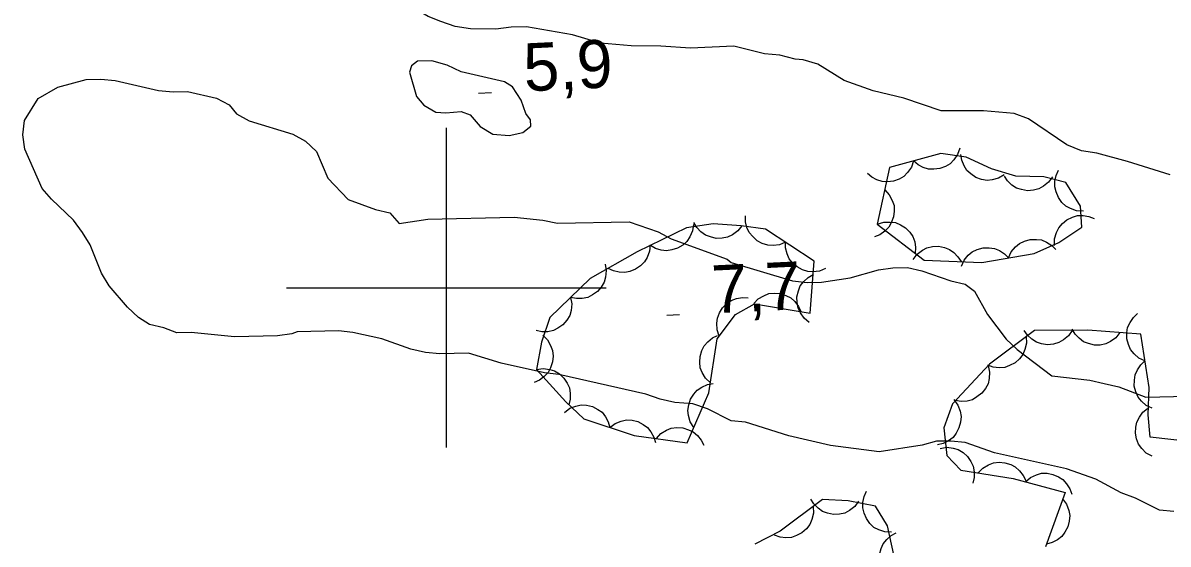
# Model space of a CAD drawing. Extents: x 336540 to 340074, y 5572036 to 5573747.
# Drawn here: x 336773.5 to 336845.2, y 5572783.9 to 5572816.6 of the extents above; entities that cross this region are included whole.
import ezdxf

# ---------------------------------------------------------------- set-up
doc = ezdxf.new("R2010")
doc.units = 0
for name, color, linetype in [('Niveau 2', 7, 'Continuous'), ('Niveau 3', 7, 'Continuous'), ('Niveau 44', 7, 'Continuous'), ('Niveau 61', 7, 'Continuous')]:
    doc.layers.add(name, color=color, linetype=linetype)

msp = doc.modelspace()

# ---------------------------------------------------------------- linework, layer by layer
at = {"layer": 'Niveau 2'}
for points in [[(336805.01, 5572816.34), (336804.05, 5572816.32), (336803.1, 5572816.18), (336801.52, 5572816.2), (336800.56, 5572816.35), (336799.65, 5572816.67), (336798.86, 5572816.99), (336798.11, 5572817.42)], [(336845.31, 5572807.07), (336842.65, 5572807.91), (336840.72, 5572808.43), (336839.76, 5572808.57), (336838.85, 5572808.95), (336836.45, 5572810.58), (336835.54, 5572810.9), (336833.62, 5572811.08), (336830.98, 5572811.08), (336828.65, 5572811.87), (336826.72, 5572812.33), (336824.91, 5572812.97), (336823.25, 5572814), (336822.34, 5572814.26), (336821.84, 5572814.3), (336820.87, 5572814.56), (336819.91, 5572814.65), (336817.99, 5572815.12), (336815.29, 5572815), (336813.43, 5572815.13), (336811.57, 5572815.14), (336809.65, 5572815.32), (336807.89, 5572815.84), (336805.01, 5572816.34)], [(336802.92, 5572809.61), (336803.94, 5572809.52), (336804.78, 5572809.71), (336805.28, 5572810.12), (336805.27, 5572810.51), (336804.98, 5572810.9), (336804.68, 5572811.74), (336804.15, 5572812.57), (336803.64, 5572812.9), (336800.92, 5572813.51), (336800.06, 5572813.94), (336799.1, 5572814.2), (336798.2, 5572814.18), (336797.81, 5572813.89), (336797.7, 5572813.5), (336798.13, 5572811.98), (336798.6, 5572811.43), (336799.34, 5572811), (336799.96, 5572810.95), (336800.92, 5572811.03), (336801.49, 5572810.82), (336802.12, 5572810.1), (336802.92, 5572809.61)], [(336803.43, 5572795.27), (336801.39, 5572795.9), (336799.59, 5572795.86), (336798.69, 5572795.95), (336797.78, 5572796.16), (336795.97, 5572796.79), (336794.15, 5572797.2), (336793.25, 5572797.29), (336790.66, 5572797.23), (336790.33, 5572797.11), (336789.43, 5572796.98), (336786.73, 5572796.92), (336784.02, 5572797.2), (336783.12, 5572797.17), (336782.32, 5572797.49), (336781.42, 5572797.7), (336780.73, 5572798.13), (336780.04, 5572798.79), (336778.88, 5572800.12), (336778.42, 5572800.9), (336777.7, 5572802.68), (336777.23, 5572803.46), (336776.65, 5572804.23), (336775.27, 5572805.55), (336774.69, 5572806.22), (336773.62, 5572808.67), (336773.49, 5572809.57), (336773.58, 5572810.47), (336774.45, 5572811.84), (336775.67, 5572812.55), (336777.46, 5572813.04), (336778.36, 5572813.06), (336779.27, 5572812.97), (336781.98, 5572812.35), (336782.89, 5572812.26), (336783.79, 5572812.28), (336785.6, 5572811.87), (336786.4, 5572811.44), (336786.86, 5572810.89), (336787.66, 5572810.45), (336790.38, 5572809.62), (336791.18, 5572809.18), (336791.87, 5572808.52), (336792.58, 5572806.85), (336793.85, 5572805.53), (336795.56, 5572804.89), (336796.46, 5572804.69), (336797.04, 5572804.02)], [(336797.04, 5572804.02), (336798.84, 5572804.29), (336804.24, 5572804.41), (336806.04, 5572804.23), (336806.95, 5572804.03), (336811.45, 5572804.13), (336813.27, 5572803.49), (336814.07, 5572803.06), (336817.59, 5572801.79), (336817.82, 5572801.57), (336821.67, 5572800.42), (336822.58, 5572800.33), (336823.48, 5572800.35), (336825.27, 5572800.61), (336827.06, 5572801.11), (336827.96, 5572801.24), (336828.86, 5572801.26), (336829.77, 5572801.05), (336831.58, 5572800.42), (336832.49, 5572800.22), (336833.06, 5572799.78), (336833.88, 5572798.33), (336835.05, 5572796.78), (336835.74, 5572796.12), (336837.91, 5572794.48), (336840.28, 5572794.2), (336841.19, 5572794), (336842.1, 5572793.79), (336843.8, 5572793.15), (336846.39, 5572793.21)], [(336845.54, 5572785.99), (336844.64, 5572786.08), (336843.15, 5572786.83), (336842.25, 5572787.15), (336840.65, 5572788.01), (336838.83, 5572788.65), (336834.31, 5572789.67), (336832.49, 5572790.31), (336831.59, 5572790.4), (336830.69, 5572790.38), (336829.79, 5572790.13), (336827.1, 5572789.73), (336824.05, 5572790.11), (336821.44, 5572790.73), (336818.72, 5572791.57), (336817.82, 5572791.66), (336816.34, 5572792.41), (336815.43, 5572792.73), (336814.3, 5572792.82), (336813.39, 5572793.02), (336812.49, 5572793.34), (336807.05, 5572794.57), (336806.15, 5572794.66), (336803.43, 5572795.27)]]:
    msp.add_lwpolyline(points, dxfattribs=at)
at = {"layer": 'Niveau 3'}
for p, q in [((336802.02, 5572812.19), (336802.82, 5572812.23)), ((336813.8, 5572798.29), (336814.6, 5572798.33))]:
    msp.add_line(p, q, dxfattribs=at)
at = {"layer": 'Niveau 44'}
for points in [[(336832.15, 5572808.73), (336832.01, 5572808.33), (336831.77, 5572808), (336831.55, 5572807.76), (336831.24, 5572807.58), (336830.9, 5572807.46), (336830.52, 5572807.42), (336830.19, 5572807.42), (336829.85, 5572807.53), (336829.53, 5572807.7), (336829.25, 5572807.94)], [(336829.25, 5572807.94), (336829.12, 5572807.54), (336828.88, 5572807.21), (336828.65, 5572806.97), (336828.35, 5572806.8), (336828, 5572806.67), (336827.62, 5572806.63), (336827.29, 5572806.64), (336826.96, 5572806.75), (336826.63, 5572806.92), (336826.36, 5572807.15)], [(336826.98, 5572803.97), (336829.91, 5572801.73), (336833.52, 5572801.57), (336836.8, 5572802.15), (336838.35, 5572802.82), (336839.79, 5572803.8), (336839.69, 5572805.1), (336838.79, 5572806.59), (336837.4, 5572806.95), (336835.65, 5572806.98), (336834.12, 5572807.44), (336832.54, 5572808.18), (336830.95, 5572808.4), (336827.75, 5572807.53), (336826.98, 5572803.97)], [(336834.93, 5572807.06), (336834.57, 5572806.85), (336834.17, 5572806.75), (336833.85, 5572806.71), (336833.5, 5572806.78), (336833.15, 5572806.9), (336832.84, 5572807.12), (336832.59, 5572807.33), (336832.41, 5572807.64), (336832.27, 5572807.98), (336832.21, 5572808.33)], [(336839.88, 5572804.79), (336839.46, 5572804.81), (336839.08, 5572804.95), (336838.79, 5572805.1), (336838.53, 5572805.34), (336838.32, 5572805.64), (336838.18, 5572806), (336838.09, 5572806.31), (336838.1, 5572806.66), (336838.18, 5572807.03), (336838.33, 5572807.35)], [(336837.94, 5572806.94), (336837.7, 5572806.6), (336837.38, 5572806.35), (336837.1, 5572806.18), (336836.76, 5572806.1), (336836.39, 5572806.07), (336836.01, 5572806.14), (336835.7, 5572806.24), (336835.41, 5572806.43), (336835.14, 5572806.69), (336834.94, 5572806.99)], [(336827.45, 5572806.12), (336827.73, 5572805.82), (336827.92, 5572805.46), (336828.03, 5572805.14), (336828.04, 5572804.79), (336828, 5572804.43), (336827.85, 5572804.07), (336827.7, 5572803.78), (336827.45, 5572803.53), (336827.14, 5572803.32), (336826.81, 5572803.19)], [(336821.24, 5572802.85), (336820.85, 5572802.69), (336820.45, 5572802.64), (336820.12, 5572802.66), (336819.78, 5572802.77), (336819.46, 5572802.94), (336819.18, 5572803.2), (336818.96, 5572803.45), (336818.82, 5572803.77), (336818.73, 5572804.13), (336818.73, 5572804.49)], [(336838.08, 5572802.64), (336838.08, 5572803.06), (336838.2, 5572803.45), (336838.34, 5572803.75), (336838.57, 5572804.01), (336838.85, 5572804.25), (336839.2, 5572804.41), (336839.51, 5572804.51), (336839.86, 5572804.52), (336840.23, 5572804.46), (336840.56, 5572804.33)], [(336805.65, 5572794.88), (336807.49, 5572792.86), (336808.61, 5572791.79), (336811.75, 5572790.75), (336815.07, 5572790.28), (336816.44, 5572793.41), (336816.95, 5572796.79), (336818.1, 5572798.32), (336819.3, 5572798.99), (336822.77, 5572798.41), (336823.03, 5572801.67), (336819.98, 5572803.67), (336818.45, 5572803.88), (336816.7, 5572804), (336815.04, 5572803.75), (336811.95, 5572802.24), (336809, 5572800.57), (336806.48, 5572798.13), (336805.96, 5572796.59), (336805.65, 5572794.88)], [(336815.47, 5572803.96), (336815.41, 5572803.55), (336815.24, 5572803.18), (336815.06, 5572802.9), (336814.8, 5572802.67), (336814.48, 5572802.48), (336814.11, 5572802.37), (336813.79, 5572802.31), (336813.44, 5572802.36), (336813.09, 5572802.46), (336812.77, 5572802.64)], [(336818.5, 5572803.88), (336818.24, 5572803.55), (336817.91, 5572803.31), (336817.61, 5572803.16), (336817.27, 5572803.1), (336816.9, 5572803.09), (336816.53, 5572803.18), (336816.22, 5572803.29), (336815.94, 5572803.5), (336815.68, 5572803.77), (336815.5, 5572804.08)], [(336826.98, 5572803.97), (336827.38, 5572804.1), (336827.78, 5572804.11), (336828.11, 5572804.08), (336828.44, 5572803.94), (336828.75, 5572803.75), (336829.01, 5572803.47), (336829.21, 5572803.21), (336829.32, 5572802.87), (336829.38, 5572802.51), (336829.36, 5572802.15)], [(336835.19, 5572801.87), (336835.36, 5572802.25), (336835.63, 5572802.55), (336835.88, 5572802.77), (336836.2, 5572802.92), (336836.55, 5572803.02), (336836.94, 5572803.02), (336837.26, 5572802.99), (336837.58, 5572802.85), (336837.9, 5572802.65), (336838.15, 5572802.39)], [(336812.75, 5572802.69), (336812.72, 5572802.28), (336812.57, 5572801.9), (336812.41, 5572801.61), (336812.15, 5572801.36), (336811.85, 5572801.15), (336811.49, 5572801.02), (336811.17, 5572800.95), (336810.82, 5572800.97), (336810.46, 5572801.05), (336810.14, 5572801.21)], [(336823.74, 5572801.2), (336823.36, 5572801.04), (336822.95, 5572801), (336822.62, 5572801.01), (336822.29, 5572801.12), (336821.97, 5572801.3), (336821.68, 5572801.56), (336821.47, 5572801.8), (336821.33, 5572802.13), (336821.24, 5572802.49), (336821.24, 5572802.85)], [(336829.22, 5572801.76), (336829.47, 5572802.1), (336829.8, 5572802.34), (336830.09, 5572802.5), (336830.43, 5572802.57), (336830.8, 5572802.59), (336831.18, 5572802.51), (336831.49, 5572802.4), (336831.77, 5572802.2), (336832.03, 5572801.93), (336832.22, 5572801.63)], [(336832.24, 5572801.34), (336832.41, 5572801.72), (336832.67, 5572802.03), (336832.92, 5572802.25), (336833.24, 5572802.4), (336833.6, 5572802.49), (336833.98, 5572802.5), (336834.31, 5572802.46), (336834.63, 5572802.32), (336834.94, 5572802.12), (336835.19, 5572801.87)], [(336809.94, 5572801.48), (336810.01, 5572801.07), (336809.96, 5572800.66), (336809.88, 5572800.34), (336809.7, 5572800.04), (336809.46, 5572799.76), (336809.14, 5572799.55), (336808.85, 5572799.39), (336808.51, 5572799.33), (336808.14, 5572799.32), (336807.78, 5572799.39)], [(336822.72, 5572797.83), (336822.4, 5572798.09), (336822.17, 5572798.42), (336822.02, 5572798.72), (336821.96, 5572799.07), (336821.95, 5572799.43), (336822.05, 5572799.81), (336822.16, 5572800.11), (336822.38, 5572800.39), (336822.65, 5572800.64), (336822.96, 5572800.82)], [(336807.78, 5572799.39), (336807.86, 5572798.98), (336807.81, 5572798.58), (336807.72, 5572798.26), (336807.54, 5572797.96), (336807.3, 5572797.68), (336806.98, 5572797.46), (336806.7, 5572797.31), (336806.35, 5572797.24), (336805.98, 5572797.23), (336805.63, 5572797.31)], [(336817.08, 5572796.97), (336816.95, 5572797.36), (336816.93, 5572797.77), (336816.97, 5572798.1), (336817.1, 5572798.42), (336817.29, 5572798.74), (336817.57, 5572799), (336817.83, 5572799.2), (336818.16, 5572799.32), (336818.53, 5572799.38), (336818.89, 5572799.37)], [(336819.24, 5572799), (336819.52, 5572799.3), (336819.88, 5572799.5), (336820.18, 5572799.63), (336820.53, 5572799.66), (336820.9, 5572799.63), (336821.26, 5572799.51), (336821.56, 5572799.37), (336821.82, 5572799.13), (336822.04, 5572798.83), (336822.19, 5572798.51)], [(336843.73, 5572795.41), (336843.35, 5572795.59), (336843.05, 5572795.86), (336842.84, 5572796.12), (336842.7, 5572796.44), (336842.61, 5572796.8), (336842.61, 5572797.18), (336842.65, 5572797.5), (336842.8, 5572797.82), (336843.01, 5572798.13), (336843.27, 5572798.38)], [(336847.56, 5572790.24), (336844.07, 5572790.65), (336843.93, 5572792.03), (336843.99, 5572793.76), (336843.47, 5572797.09), (336840.16, 5572797.34), (336836.82, 5572797.32), (336834, 5572795.22), (336831.68, 5572792.72), (336831.14, 5572791.23), (336831.33, 5572789.5), (336832.2, 5572788.57), (336835.49, 5572788.05), (336838.73, 5572787.18), (336837.51, 5572783.77)], [(336839.18, 5572797.33), (336838.95, 5572796.99), (336838.63, 5572796.73), (336838.35, 5572796.56), (336838.01, 5572796.46), (336837.64, 5572796.43), (336837.26, 5572796.49), (336836.95, 5572796.58), (336836.65, 5572796.77), (336836.38, 5572797.02), (336836.18, 5572797.32)], [(336842.17, 5572797.19), (336841.91, 5572796.86), (336841.58, 5572796.63), (336841.28, 5572796.48), (336840.94, 5572796.41), (336840.57, 5572796.41), (336840.2, 5572796.5), (336839.89, 5572796.61), (336839.61, 5572796.83), (336839.36, 5572797.1), (336839.18, 5572797.41)], [(336806.04, 5572797.02), (336806.34, 5572796.73), (336806.53, 5572796.38), (336806.65, 5572796.07), (336806.68, 5572795.72), (336806.65, 5572795.35), (336806.52, 5572794.99), (336806.37, 5572794.69), (336806.13, 5572794.44), (336805.83, 5572794.22), (336805.5, 5572794.07)], [(336816.54, 5572794.04), (336816.23, 5572794.33), (336816.02, 5572794.68), (336815.89, 5572794.98), (336815.86, 5572795.33), (336815.88, 5572795.7), (336816, 5572796.06), (336816.13, 5572796.36), (336816.37, 5572796.62), (336816.66, 5572796.86), (336816.98, 5572797.01)], [(336836.3, 5572796.94), (336836.32, 5572796.52), (336836.22, 5572796.12), (336836.1, 5572795.82), (336835.88, 5572795.54), (336835.6, 5572795.3), (336835.26, 5572795.12), (336834.96, 5572795.01), (336834.61, 5572794.99), (336834.24, 5572795.03), (336833.9, 5572795.14)], [(336833.91, 5572795.13), (336834.01, 5572794.72), (336833.98, 5572794.31), (336833.92, 5572793.99), (336833.75, 5572793.68), (336833.52, 5572793.39), (336833.22, 5572793.16), (336832.94, 5572792.98), (336832.6, 5572792.9), (336832.23, 5572792.87), (336831.87, 5572792.93)], [(336844.19, 5572792.45), (336843.82, 5572792.63), (336843.52, 5572792.9), (336843.3, 5572793.15), (336843.16, 5572793.47), (336843.07, 5572793.83), (336843.08, 5572794.22), (336843.12, 5572794.54), (336843.26, 5572794.86), (336843.47, 5572795.17), (336843.73, 5572795.41)], [(336805.65, 5572794.88), (336806.06, 5572794.94), (336806.47, 5572794.88), (336806.78, 5572794.79), (336807.08, 5572794.6), (336807.35, 5572794.34), (336807.56, 5572794.02), (336807.7, 5572793.73), (336807.76, 5572793.38), (336807.75, 5572793.01), (336807.67, 5572792.66)], [(336815.49, 5572791.25), (336815.27, 5572791.6), (336815.16, 5572791.99), (336815.12, 5572792.32), (336815.17, 5572792.67), (336815.29, 5572793.02), (336815.5, 5572793.34), (336815.71, 5572793.59), (336816, 5572793.78), (336816.34, 5572793.93), (336816.7, 5572794)], [(336831.78, 5572792.99), (336832.02, 5572792.65), (336832.16, 5572792.26), (336832.22, 5572791.94), (336832.19, 5572791.59), (336832.09, 5572791.23), (336831.91, 5572790.9), (336831.72, 5572790.63), (336831.43, 5572790.42), (336831.1, 5572790.25), (336830.75, 5572790.17)], [(336807.39, 5572792.19), (336807.72, 5572792.45), (336808.11, 5572792.59), (336808.43, 5572792.67), (336808.78, 5572792.64), (336809.14, 5572792.56), (336809.48, 5572792.38), (336809.75, 5572792.2), (336809.96, 5572791.92), (336810.14, 5572791.6), (336810.24, 5572791.25)], [(336844.19, 5572789.45), (336843.82, 5572789.64), (336843.54, 5572789.93), (336843.34, 5572790.2), (336843.21, 5572790.53), (336843.15, 5572790.89), (336843.17, 5572791.27), (336843.23, 5572791.59), (336843.39, 5572791.9), (336843.61, 5572792.2), (336843.89, 5572792.43)], [(336810.24, 5572791.25), (336810.57, 5572791.5), (336810.95, 5572791.65), (336811.27, 5572791.72), (336811.63, 5572791.7), (336811.99, 5572791.62), (336812.32, 5572791.44), (336812.59, 5572791.25), (336812.81, 5572790.98), (336812.99, 5572790.65), (336813.09, 5572790.31)], [(336813.15, 5572790.55), (336813.43, 5572790.86), (336813.78, 5572791.07), (336814.08, 5572791.2), (336814.43, 5572791.24), (336814.8, 5572791.22), (336815.16, 5572791.11), (336815.46, 5572790.98), (336815.73, 5572790.74), (336815.96, 5572790.46), (336816.12, 5572790.13)], [(336830.91, 5572789.94), (336831.33, 5572790.01), (336831.73, 5572789.95), (336832.05, 5572789.87), (336832.35, 5572789.68), (336832.62, 5572789.43), (336832.83, 5572789.11), (336832.98, 5572788.82), (336833.04, 5572788.48), (336833.04, 5572788.11), (336832.96, 5572787.75)], [(336833.3, 5572788.4), (336833.59, 5572788.7), (336833.94, 5572788.9), (336834.25, 5572789.03), (336834.6, 5572789.07), (336834.96, 5572789.04), (336835.33, 5572788.92), (336835.62, 5572788.78), (336835.88, 5572788.54), (336836.11, 5572788.25), (336836.27, 5572787.93)], [(336836.25, 5572787.85), (336836.57, 5572788.12), (336836.94, 5572788.28), (336837.25, 5572788.38), (336837.61, 5572788.38), (336837.97, 5572788.31), (336838.32, 5572788.15), (336838.6, 5572787.99), (336838.83, 5572787.72), (336839.03, 5572787.41), (336839.15, 5572787.07)], [(336827.87, 5572784.69), (336827.45, 5572784.71), (336827.07, 5572784.84), (336826.77, 5572784.99), (336826.52, 5572785.24), (336826.3, 5572785.54), (336826.16, 5572785.89), (336826.07, 5572786.21), (336826.08, 5572786.56), (336826.15, 5572786.92), (336826.3, 5572787.25)], [(336828.02, 5572783.27), (336827.62, 5572785.09), (336826.87, 5572786.32), (336825.15, 5572786.66), (336823.55, 5572786.73), (336820.9, 5572784.76), (336819.32, 5572783.94)], [(336825.81, 5572786.63), (336825.57, 5572786.3), (336825.24, 5572786.05), (336824.95, 5572785.89), (336824.61, 5572785.82), (336824.24, 5572785.8), (336823.86, 5572785.88), (336823.55, 5572785.99), (336823.27, 5572786.19), (336823.01, 5572786.46), (336822.82, 5572786.76)], [(336838.58, 5572786.77), (336838.83, 5572786.44), (336838.97, 5572786.05), (336839.03, 5572785.73), (336839, 5572785.38), (336838.91, 5572785.02), (336838.72, 5572784.69), (336838.53, 5572784.42), (336838.25, 5572784.21), (336837.92, 5572784.04), (336837.57, 5572783.95)], [(336822.96, 5572786.29), (336822.98, 5572785.88), (336822.88, 5572785.48), (336822.76, 5572785.18), (336822.54, 5572784.9), (336822.26, 5572784.65), (336821.92, 5572784.48), (336821.61, 5572784.36), (336821.26, 5572784.34), (336820.89, 5572784.38), (336820.55, 5572784.5)], [(336827.85, 5572781.67), (336827.53, 5572781.94), (336827.31, 5572782.28), (336827.17, 5572782.58), (336827.11, 5572782.93), (336827.12, 5572783.3), (336827.23, 5572783.67), (336827.35, 5572783.97), (336827.57, 5572784.24), (336827.85, 5572784.49), (336828.17, 5572784.65)]]:
    msp.add_lwpolyline(points, dxfattribs=at)
at = {"layer": 'Niveau 61'}
for points in [[(336800, 5572790), (336800, 5572810)], [(336790, 5572800), (336810, 5572800)]]:
    msp.add_lwpolyline(points, dxfattribs=at)

# ---------------------------------------------------------------- texts
at = {"layer": 'Niveau 3'}
for s, p in [('5,9    ', (336804.9, 5572812.29)), ('7,7    ', (336816.68, 5572798.39))]:
    msp.add_text(s, height=3, rotation=2.7712, dxfattribs=at).set_placement(p)

doc.saveas('drawing.dxf')
